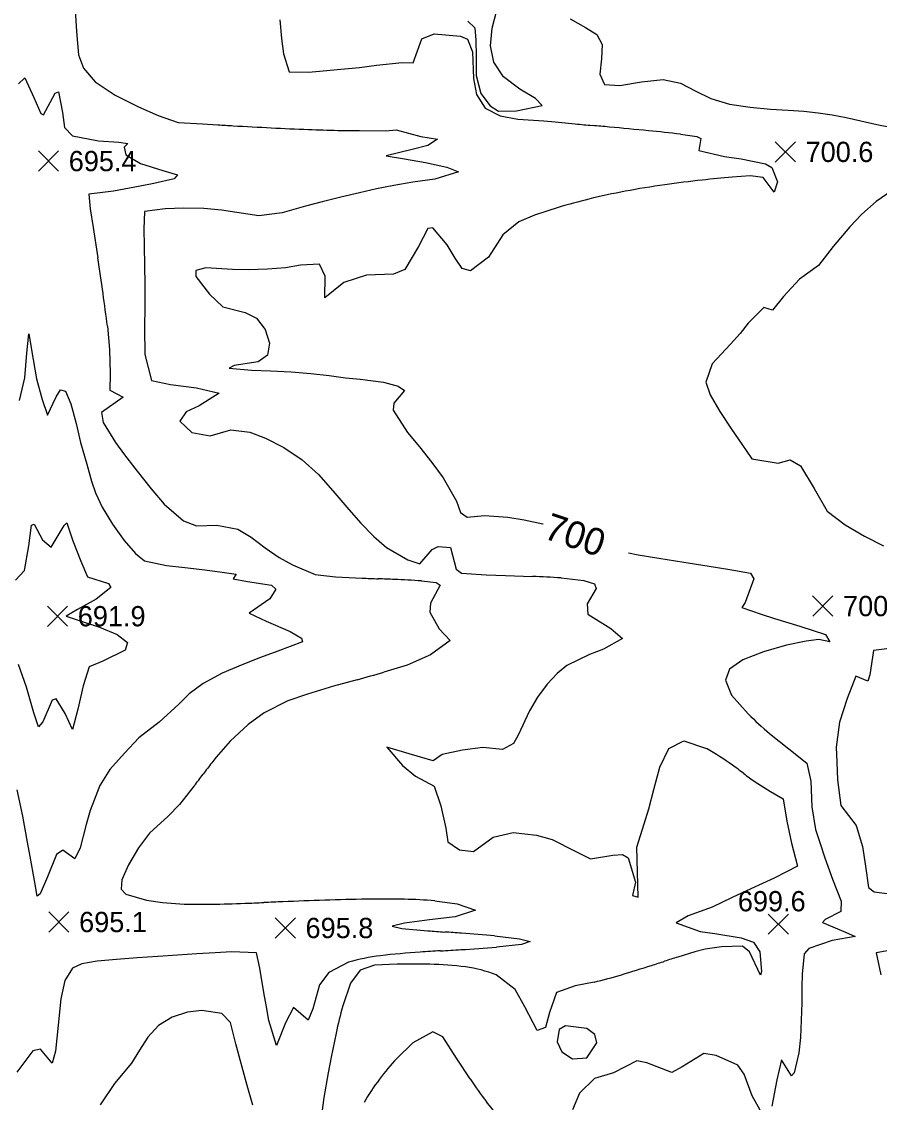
# Model space of a CAD drawing. Extents: x 2566079 to 2571326, y 424054 to 426896.
# Drawn here: x 2567271 to 2567906, y 425294 to 426094 of the extents above; entities that cross this region are included whole.
import ezdxf

# ---------------------------------------------------------------- set-up
doc = ezdxf.new("R2010")
doc.units = 0
for name, color, linetype in [('Contour_ADS_Label_Major', 7, 'Continuous'), ('Contour_ADS_Major', 7, 'Continuous'), ('Contour_ADS_Minor', 7, 'Continuous'), ('Contour_ADS_Spot_Elevation', 7, 'Continuous')]:
    doc.layers.add(name, color=color, linetype=linetype)

# ---------------------------------------------------------------- blocks, each defined once
blk = doc.blocks.new('S750')
at = {"layer": 'Contour_ADS_Spot_Elevation'}
for p, q in [((-0.5, 0.498), (0.5, -0.498)), ((-0.498, -0.5), (0.498, 0.5))]:
    blk.add_line(p, q, dxfattribs=at)

msp = doc.modelspace()

# ---------------------------------------------------------------- linework, layer by layer
at = {"layer": 'Contour_ADS_Major'}
for points in [[(2567462.34, 426095.16), (2567463.66, 426081.33), (2567465.22, 426069.89), (2567469.25, 426056.61), (2567483.55, 426056.31), (2567494.38, 426057.49), (2567507.57, 426058.6), (2567521.31, 426059.91), (2567534.02, 426061.5), (2567553, 426063.65), (2567561, 426063.42), (2567567.4, 426081.06), (2567576.52, 426084.87), (2567596.19, 426083.11), (2567601.2, 426080.96), (2567604.98, 426071.58), (2567605.65, 426051.77), (2567608.08, 426039.79), (2567614.38, 426029.9), (2567625.51, 426024.11), (2567638.68, 426021.59), (2567657.82, 426020.31), (2567666.12, 426019.58), (2567681.09, 426018.16)], [(2567759.03, 426010.59), (2567771.08, 426008.87), (2567774.11, 426007.48), (2567772.56, 425998.57), (2567791.4, 425994.16), (2567803.88, 425992.25), (2567821.79, 425988.7), (2567826.59, 425985.98), (2567830.65, 425975.24), (2567828.36, 425967.78), (2567820.04, 425978.4), (2567810.51, 425979.65), (2567797.15, 425978.78)], [(2567668.45, 425956.35), (2567650.9, 425950.53), (2567639.21, 425945.6), (2567627.37, 425936.13), (2567616.83, 425919.57), (2567603.5, 425909.36), (2567597.34, 425911.15), (2567592.18, 425918.77), (2567586.17, 425928.64), (2567575.71, 425941.37), (2567571.92, 425940.89), (2567565.17, 425927.49), (2567554.83, 425910.41), (2567546.45, 425907.11), (2567526.63, 425906.14), (2567509.79, 425900.74), (2567495.72, 425889.42), (2567496.01, 425905.51), (2567491.79, 425914.35), (2567477.61, 425913.59), (2567466.53, 425911.76), (2567453.23, 425910.62), (2567439.5, 425910.26), (2567427.47, 425910.49), (2567407.77, 425911.78), (2567400.33, 425909.65), (2567400.28, 425905.19), (2567410.49, 425892.32), (2567420.32, 425882.75), (2567436.77, 425878.74), (2567445.09, 425874.4), (2567451.57, 425866.05), (2567454.78, 425855.92), (2567453.28, 425847.19), (2567446.46, 425842.25), (2567428.71, 425839.39), (2567424.95, 425837.34), (2567441.52, 425835.92), (2567455.63, 425835.51), (2567470.88, 425834.81), (2567485.41, 425833.52), (2567498.81, 425831.92), (2567510.99, 425830.39), (2567521.87, 425829.21), (2567539.17, 425827.12), (2567549.88, 425824.08), (2567554.59, 425820.95), (2567546.68, 425811.64), (2567546.21, 425806.44), (2567556.91, 425789.97), (2567565.75, 425779.29), (2567574.98, 425767.65), (2567583.35, 425756.21), (2567593.07, 425739.01), (2567596.05, 425730.63), (2567601.01, 425727.25), (2567613.93, 425728.56), (2567631.26, 425727.3), (2567643.37, 425725.27), (2567657.06, 425722.27), (2567657.23, 425722.23)], [(2567720.39, 425700.91), (2567727.7, 425699.42), (2567742.86, 425696.85), (2567761.33, 425693.9), (2567780.11, 425690.96), (2567795.43, 425688.56), (2567810.75, 425685.73), (2567813.29, 425681.58), (2567806.78, 425664.12), (2567804.33, 425660.5), (2567818.61, 425655.49), (2567828.56, 425652.32), (2567847.24, 425646.53), (2567866.17, 425640.35), (2567869.43, 425634.94), (2567861.34, 425636.71), (2567852.08, 425635.58), (2567837.4, 425632.43), (2567820.39, 425627.59), (2567805.17, 425621.65), (2567795.28, 425614.9), (2567792.19, 425606.57), (2567796.8, 425595.6), (2567809.03, 425581.65)], [(2567824.84, 425567.27), (2567839.16, 425555.73), (2567852.51, 425545.17), (2567855.33, 425531.87), (2567856.17, 425513.01), (2567858.91, 425496.27), (2567862.06, 425486.45), (2567865.85, 425475.16), (2567871.53, 425459.39), (2567877.77, 425443.09), (2567877.55, 425435.4), (2567866.03, 425429.52), (2567863.95, 425427.48), (2567880.98, 425420.33), (2567888.11, 425417.04), (2567871.26, 425413.98), (2567854.01, 425408.1), (2567850.4, 425404.16), (2567849.06, 425389.2), (2567848.86, 425379.81), (2567848.69, 425368.04), (2567848.37, 425355.04), (2567847.68, 425342.24), (2567846.48, 425330.94), (2567843.06, 425316.13), (2567841.15, 425313.85), (2567833.72, 425325.75), (2567830.13, 425311.01), (2567826.49, 425291.4)], [(2567603.32, 425311.59), (2567593.25, 425326.89), (2567582.98, 425342.73), (2567575.74, 425346.51), (2567560.86, 425338.44), (2567549.01, 425326.84)], [(2567820.05, 425284.63), (2567811.99, 425299.22), (2567806, 425315.05), (2567801.34, 425321.76), (2567785.32, 425329.05), (2567776.28, 425330.43), (2567760.12, 425320.52), (2567752.59, 425316.46), (2567734.01, 425323.45), (2567726.56, 425325), (2567709.44, 425316.16), (2567695.41, 425311.87), (2567684.1, 425301.07), (2567678.97, 425288.67)], [(2567626.89, 425280.36), (2567615.34, 425294.59)]]:
    msp.add_lwpolyline(points, dxfattribs=at)
msp.add_lwpolyline([(2567667.64, 425339.06), (2567671.02, 425331.64), (2567678.96, 425326.53), (2567689.66, 425327.29), (2567696.93, 425338.29), (2567695.66, 425344.48), (2567689.7, 425348.94), (2567673.73, 425350.88), (2567669.21, 425348.09), (2567667.64, 425339.06)], close=True, dxfattribs=at)
for centre, radius, start, end in [((2568706.55, 436984.47), 11014.15, 264.657814, 264.723589), ((2566534.64, 413476.57), 12593.87, 84.661939, 84.719464), ((2566982.3, 418237.87), 7811.57, 84.468856, 84.682225), ((2567566.58, 424279.18), 1742.08, 83.65765, 84.44466), ((2567841.53, 425299.9), 679.76, 97.97351, 100.46715), ((2567871.15, 425103.53), 878.34, 96.28207, 98.10999), ((2567858.79, 425243.76), 737.6, 94.79374, 96.51968), ((2567813.93, 425460.03), 517.28, 100.68282, 103.72253), ((2567793.69, 425540.62), 434.19, 103.65118, 106.76536), ((2567988.45, 425763.03), 255.13, 225.31143, 230.11234), ((2567682.02, 425202.72), 181.93, 136.98036, 143.3136), ((2567659.57, 425217.49), 155.11, 142.73318, 150.32027), ((2567967.9, 425556.62), 439.27, 213.9046, 216.62052)]:
    msp.add_arc(centre, radius, start, end, dxfattribs=at)
at = {"layer": 'Contour_ADS_Minor'}
for points in [[(2567246.02, 426227.22), (2567260.29, 426234.98), (2567265.45, 426231.12), (2567270.63, 426234.47), (2567276.99, 426224.58), (2567283.12, 426207.93), (2567287.63, 426192.52), (2567294.86, 426177.28), (2567304.09, 426161.8), (2567306.68, 426151.66), (2567308.54, 426137.36), (2567309.79, 426121.24), (2567310.64, 426106.44), (2567311.82, 426086.51), (2567313.44, 426069.32), (2567317.06, 426059.43), (2567325.67, 426049.24), (2567340.46, 426039.34), (2567357.71, 426030.67), (2567372.46, 426024.26), (2567387.1, 426019.15), (2567405.23, 426018.1), (2567416.59, 426017.44)], [(2567601.46, 426094.19), (2567606.62, 426089.26), (2567607.58, 426080.12), (2567607.76, 426068.22), (2567607.8, 426054.03), (2567611.23, 426040.56), (2567618.19, 426031.46), (2567624.28, 426027.66), (2567637.61, 426027.94), (2567656.62, 426031.85), (2567651.68, 426036.83), (2567640, 426043.95), (2567628, 426053.02), (2567620.82, 426063.77), (2567618.44, 426075.91), (2567619.54, 426089.06), (2567623.1, 426102.39)], [(2567677.28, 426096), (2567688.74, 426089.58), (2567697.02, 426084.23), (2567700.95, 426077.01), (2567700.37, 426066.22), (2567699.27, 426054.93), (2567702.67, 426047.43), (2567713.94, 426046.55), (2567730.02, 426049.21), (2567746.21, 426050.89), (2567759.02, 426048.24), (2567769.85, 426042.69), (2567781.3, 426036.86), (2567795.25, 426032.81), (2567810.61, 426030.45), (2567825.58, 426029.13), (2567838.74, 426028.28), (2567850.31, 426027.5), (2567860.89, 426026.44), (2567871.1, 426024.86), (2567881.44, 426022.8)], [(2567268.91, 426047.81), (2567273.81, 426052.36), (2567280.29, 426037.69), (2567285.61, 426025.95), (2567287.47, 426024.97), (2567296.27, 426040.88), (2567298.68, 426041.97), (2567301.63, 426026.67), (2567303.15, 426015.39), (2567308.96, 426009.31), (2567328.32, 426005.71), (2567343.22, 426004.77), (2567349.9, 426003.64), (2567347.21, 426001.07), (2567348.42, 425995.32), (2567359.36, 425988.79), (2567375.84, 425983.68), (2567386.64, 425980.41), (2567384.26, 425977.59), (2567369.09, 425974.11), (2567359.02, 425972.07), (2567339.41, 425968.45), (2567321.12, 425966.29), (2567322.15, 425955.33), (2567324.26, 425941.54), (2567327.69, 425919.09)], [(2567881.44, 426022.8), (2567892.44, 426020.4), (2567904.25, 426017.83), (2567915.64, 426015.39)], [(2567505.47, 426013.38), (2567521.34, 426013.17), (2567540.93, 426012.93), (2567548.43, 426013.82), (2567566.66, 426008.89), (2567579.1, 426006.83), (2567571.97, 426002.12), (2567560.45, 425999.13), (2567541.09, 425994.61), (2567554.76, 425992.29), (2567570.23, 425989.55), (2567586.1, 425986.11), (2567594.63, 425982.67), (2567577.11, 425977.27), (2567560.94, 425974.96), (2567546.67, 425972.59), (2567533.98, 425970.03), (2567521.28, 425967.16), (2567507.51, 425963.92), (2567493.69, 425960.55), (2567481.37, 425957.36), (2567464.25, 425952.42), (2567446.8, 425950.11), (2567430.49, 425952.58), (2567419.25, 425954.38), (2567406.06, 425955.65), (2567391.46, 425955.89), (2567377.66, 425955.3), (2567362.17, 425953.25), (2567361.81, 425940.18), (2567361.98, 425927.86), (2567362.23, 425913.09), (2567362.47, 425899.6), (2567362.59, 425883.07), (2567362.2, 425866.94), (2567362.48, 425847.55), (2567367.44, 425828.22), (2567381.49, 425825.3), (2567400.81, 425822.8), (2567417.56, 425818.99), (2567402.66, 425809.71), (2567393.05, 425805.12), (2567388.31, 425798.19), (2567397.41, 425789.9), (2567410.78, 425787.31), (2567426.23, 425791.93), (2567440.14, 425790.06), (2567451.74, 425785.63), (2567465.33, 425778.76), (2567478.93, 425769.7), (2567490.99, 425758.77), (2567501.76, 425746.77), (2567511.96, 425734.6), (2567522.12, 425723.11), (2567532.05, 425712.99), (2567541.43, 425704.89), (2567557.08, 425695.71), (2567566.14, 425692.62), (2567575.16, 425703.43), (2567579.56, 425705.6), (2567588.78, 425704.69), (2567592.98, 425688.76), (2567596.75, 425685.74), (2567615.14, 425684.57), (2567629.4, 425684.07), (2567649.36, 425683.38)], [(2567915.53, 425968.98), (2567903.71, 425960.74), (2567893.14, 425951.35), (2567884.21, 425942.06), (2567872.01, 425927.35), (2567861.1, 425913.51), (2567846.91, 425903.4), (2567835.2, 425890.46), (2567826.94, 425880.29), (2567820.65, 425882.26), (2567809.03, 425870.74), (2567803.06, 425863.05), (2567795.87, 425855.25), (2567782.32, 425840.75), (2567777.77, 425827.03), (2567780.9, 425817.67), (2567787.94, 425805.42), (2567796.71, 425792.34), (2567804.42, 425781.19), (2567811.71, 425770.27), (2567831.17, 425767.06), (2567840.23, 425769.53), (2567847.81, 425765.22), (2567857.99, 425748.43), (2567867.57, 425731.71), (2567880.81, 425721.53), (2567895.16, 425713.28), (2567909.11, 425705.91)], [(2567334.77, 425868.42), (2567336.41, 425851.19), (2567336.74, 425833.19), (2567336.6, 425821.3), (2567346.51, 425816.04), (2567330.55, 425804.66), (2567331.63, 425797.22), (2567340.8, 425782.47), (2567347.58, 425773.36), (2567356.78, 425761.24), (2567367.13, 425748.16), (2567376.94, 425736.74), (2567391.22, 425724.49), (2567400.71, 425720.85), (2567415.78, 425721.41), (2567431.36, 425718.36), (2567441.09, 425712.39), (2567451.53, 425704.66), (2567462.02, 425697.28), (2567471.81, 425691.91), (2567488.53, 425684.78), (2567503.57, 425682.98), (2567523.46, 425682.12)], [(2567269.65, 425813.65), (2567273.7, 425830.28), (2567275.24, 425848.61), (2567276.76, 425862.95), (2567279.83, 425843.77), (2567282.38, 425829.54), (2567286.41, 425814.3), (2567290.57, 425802.75), (2567296.85, 425816.17), (2567300.03, 425821.31), (2567303.74, 425820.55), (2567307.73, 425811.08), (2567311.63, 425796.62), (2567315, 425782.5), (2567319.51, 425766.32), (2567323.11, 425753.81), (2567326.07, 425745.16), (2567331.04, 425734.52), (2567338.55, 425722.15), (2567347.3, 425709.97), (2567355.51, 425700.35), (2567362.14, 425694.94), (2567378.44, 425691.38), (2567392.02, 425689.89), (2567407, 425688.16), (2567419.66, 425686.65), (2567430.08, 425684.98), (2567427.86, 425681.72), (2567438.44, 425679.59), (2567456.21, 425676.83), (2567459.43, 425674.06), (2567454.94, 425666.72), (2567439.67, 425656.11), (2567452.41, 425650.17), (2567470.18, 425642.68), (2567478.53, 425637.76), (2567479.29, 425634.88), (2567460.88, 425628.04), (2567448.21, 425623.31), (2567435.15, 425618.3), (2567419.75, 425611.73), (2567405.56, 425604.28), (2567395.21, 425596.55), (2567387.61, 425588.96), (2567373.17, 425575.63), (2567357.97, 425564.07), (2567347.45, 425552.54), (2567336.51, 425540.62), (2567329.26, 425528.72), (2567322.08, 425510.12), (2567319.2, 425499.88), (2567314.61, 425482.71), (2567310.62, 425474.47), (2567301.81, 425480.95), (2567297.06, 425477.79), (2567290.48, 425461.12), (2567285.11, 425448.54), (2567282.74, 425446.87), (2567280.88, 425458.56), (2567277.56, 425476.31), (2567275.65, 425486.82), (2567272.24, 425505.93), (2567267.97, 425525.4)], [(2567266.72, 425680.67), (2567273.47, 425687.73), (2567276.76, 425705.99), (2567278.69, 425721.2), (2567280.72, 425722.14), (2567286.69, 425710.39), (2567293.22, 425704.96), (2567302.73, 425720.99), (2567304.81, 425723.03), (2567309.3, 425709.68), (2567315.16, 425694.7), (2567320.09, 425682.98), (2567335.74, 425678.13), (2567337.43, 425675.11), (2567326.5, 425666.5), (2567312.64, 425658.97), (2567304.24, 425654.02), (2567316.24, 425649.97), (2567328.91, 425645.77), (2567342.05, 425640.36), (2567349.76, 425634.51), (2567347.99, 425628.94), (2567331.39, 425620.59), (2567321.39, 425616.44), (2567316.87, 425602.37), (2567312.88, 425585.25), (2567308.88, 425570.13), (2567303.55, 425581.87), (2567296.97, 425592.75), (2567293.89, 425591.76), (2567286.91, 425575.81), (2567283.69, 425572.22), (2567280.35, 425582.56), (2567274.88, 425601.39), (2567269.04, 425618.18)], [(2567567.24, 425680.1), (2567578.01, 425678.83), (2567581, 425676.93), (2567574.05, 425663.49), (2567573.52, 425657.03), (2567580.26, 425644.5), (2567588.51, 425635.98), (2567574, 425625.35), (2567556.63, 425617.81), (2567539.37, 425612.53)], [(2567670.56, 425682.27), (2567687.29, 425680.49), (2567695.35, 425677.86), (2567696.62, 425674.56), (2567689.84, 425663.02), (2567690.47, 425655.42), (2567707.36, 425644.86), (2567716.11, 425637.58), (2567702.06, 425629.53), (2567691.55, 425625.6), (2567674.86, 425617.49), (2567667.63, 425611.61), (2567660.25, 425603.58), (2567653.15, 425594.05), (2567647.08, 425583.97), (2567638.81, 425565.97), (2567635.25, 425559.84), (2567627.26, 425555.39), (2567612.75, 425556.92), (2567597.66, 425554.82), (2567582.53, 425551.76), (2567575.8, 425547.08), (2567558.24, 425552.08), (2567541.6, 425556.96), (2567553.32, 425543.44), (2567562.91, 425535.54), (2567576.71, 425528.31), (2567581.58, 425513.72), (2567585.3, 425497.06), (2567586.81, 425487.15), (2567595.34, 425481.03), (2567605.7, 425479.83), (2567620.32, 425490.42), (2567635.06, 425493.91), (2567652.44, 425492.03), (2567663.96, 425488.81), (2567681.09, 425480.09), (2567692.25, 425474.52), (2567708.91, 425477.23), (2567716.08, 425477.66), (2567720.14, 425475.1), (2567725.68, 425457.28), (2567723.44, 425447.4), (2567727.68, 425446.18), (2567727.02, 425464.49), (2567726.61, 425483.19), (2567732.08, 425500.43), (2567735.44, 425511.5), (2567739.24, 425525.8), (2567743.57, 425542.2), (2567750.22, 425556.06), (2567761.42, 425561.88), (2567778.24, 425556.18)], [(2567919.35, 425630.89), (2567901.89, 425628.69), (2567899.14, 425610.56), (2567897.53, 425605.83), (2567888.66, 425609.7), (2567882.27, 425593.14), (2567876.58, 425575.68), (2567874.18, 425557.06), (2567874.55, 425545.9), (2567875.21, 425532.98), (2567877.61, 425513.93), (2567888.9, 425499.06), (2567893.76, 425483.48), (2567895.98, 425469.01), (2567898.2, 425453.36), (2567902.37, 425450.16), (2567921.32, 425447.49)], [(2567519.6, 425606.97), (2567502.03, 425602.08), (2567483.02, 425596.27), (2567468.22, 425591.34), (2567450.93, 425582.46), (2567438.91, 425573.92), (2567425.64, 425561.6)], [(2567814.22, 425531.37), (2567825.45, 425524.25), (2567834.96, 425518.9), (2567837.59, 425502.39), (2567841.18, 425486.11), (2567845.63, 425469.15), (2567828.33, 425460.27), (2567810.97, 425452.39), (2567797.29, 425445.91), (2567782.34, 425438.74), (2567764.72, 425432.25), (2567755.81, 425427.09), (2567773.49, 425420.82), (2567784.32, 425419.13), (2567803.94, 425415.96), (2567812.9, 425412.79), (2567817.55, 425405.76), (2567818.94, 425391.23), (2567818.06, 425388.42), (2567809.96, 425405.61), (2567804.84, 425409.92), (2567789.21, 425409.43), (2567777.13, 425407.52), (2567769.5, 425405.61), (2567756.89, 425401.81)], [(2567399.14, 425528.53), (2567388.16, 425514.56), (2567379.77, 425506.04), (2567365.89, 425493.39), (2567357.87, 425482.55), (2567350.35, 425469.93), (2567345.51, 425458.89), (2567344.99, 425451.95), (2567348.41, 425448.23), (2567363.78, 425443.95), (2567375.7, 425442.12), (2567391.52, 425440.99)], [(2567577.18, 425443.34), (2567593.55, 425441.24), (2567607.29, 425436.38), (2567592.07, 425431.65), (2567573.21, 425429.22), (2567554.66, 425426.86), (2567545.64, 425424.71), (2567552.72, 425422.88), (2567572.01, 425421.2)], [(2567621.34, 425417.5), (2567639.9, 425415.37), (2567647.67, 425413.2), (2567641.17, 425411.1), (2567622.81, 425409.11)], [(2567513.16, 425397.96), (2567498.75, 425390.43), (2567491.69, 425381.21), (2567486.95, 425363.58), (2567483.37, 425355.13), (2567472.59, 425364.37), (2567466.71, 425353.04), (2567459.91, 425336.42), (2567454.16, 425354.84), (2567452.44, 425365.02), (2567450.67, 425375.63), (2567447.59, 425393.66), (2567445.19, 425404.82), (2567426.56, 425405.64), (2567414.56, 425405.01), (2567400.93, 425404.17), (2567386.71, 425403.2), (2567372.06, 425402.16), (2567356.9, 425401.13), (2567341.44, 425400.1), (2567327.2, 425398.75), (2567315.95, 425396.7), (2567308.96, 425393.64), (2567303.26, 425384.4), (2567300.43, 425370.82), (2567298.34, 425351.48), (2567296.41, 425332.1), (2567293.88, 425323.33), (2567285.4, 425333.61), (2567279.52, 425332.34), (2567267.72, 425316.68)], [(2567913.35, 425406.75), (2567903.67, 425404.85), (2567907.29, 425388.71)], [(2567549.35, 425396.47), (2567532.59, 425395.71), (2567521.97, 425392.05), (2567514.82, 425382.54), (2567508.96, 425365.64)], [(2567695.03, 425383.22), (2567680.89, 425380.56), (2567667.08, 425375.63), (2567662.11, 425360.83), (2567659.08, 425349.77), (2567652.76, 425347.4), (2567643.68, 425365.07), (2567636.57, 425377.8), (2567622.57, 425388.61)], [(2567442.33, 425292.13), (2567438.29, 425306.78), (2567433.73, 425323.11), (2567429.89, 425337.53), (2567425.88, 425353.3), (2567419.42, 425359.97), (2567404.7, 425362.34), (2567394.09, 425360.94), (2567382.81, 425357.36), (2567372.61, 425351.26), (2567364.76, 425342.64), (2567358.54, 425332.8), (2567352.73, 425323.34), (2567340.01, 425308.35), (2567329.56, 425292.5)], [(2567504.11, 425345.51), (2567500.47, 425327.75), (2567498.12, 425316.22), (2567494.94, 425297.8), (2567492.94, 425282.9)]]:
    msp.add_lwpolyline(points, dxfattribs=at)
for centre, radius, start, end in [((2567808.26, 432762.96), 6756.88, 266.676961, 266.773447), ((2567714.18, 431086.32), 5077.61, 266.76841, 267.08629), ((2567582.68, 428496.58), 2484.53, 267.07919, 267.71379), ((2567534.75, 427369.22), 1356.15, 267.83711, 268.76277), ((2564440.66, 425480.83), 2920.1, 8.10744, 8.63181), ((2566207.7, 425732.36), 1135.26, 6.88341, 8.11686), ((2567620.22, 424923.88), 760.06, 86.20264, 87.803), ((2567851.11, 433630.94), 7955.57, 267.639636, 267.725122), ((2567471.07, 423948.95), 1733.88, 87.48448, 87.87638), ((2567505.1, 424694.12), 987.93, 86.39391, 87.55953), ((2566517.11, 429209.52), 3739.44, 285.55046, 285.86513), ((2567639.67, 425367.17), 289.16, 137.74733, 141.93289), ((2567657.46, 425349.96), 238.99, 54.17734, 59.6421), ((2567740.01, 425289.4), 416.11, 142.02059, 143.48574), ((2567566.87, 425219.76), 397.59, 53.06538, 54.57407), ((2566439.69, 426265.57), 1209.87, 322.46879, 322.9723), ((2567959.47, 425738.27), 252.79, 232.55701, 234.92943), ((2567932.65, 413579.78), 11872.13, 92.109392, 92.258819), ((2567555.74, 423695.81), 1749.08, 90.95252, 91.96803), ((2567538.76, 424679.75), 764.99, 88.80717, 90.90666), ((2567545.3, 425069.74), 374.96, 85.12301, 88.56531), ((2567404.5, 425916.19), 475.38, 268.43479, 270.89016), ((2567383.66, 426885.28), 1444.69, 271.11949, 272.09512), ((2567355.83, 427655.18), 2215.09, 272.08667, 272.45244), ((2568301.04, 404177.34), 21281.78, 92.252142, 92.290186), ((2567668.05, 426708.95), 1291.33, 265.73473, 266.28981), ((2567432.32, 423147.5), 2277.92, 85.85494, 86.16961), ((2567492.16, 423963.75), 1459.47, 84.92188, 85.88169), ((2567605.22, 424825.86), 580.93, 93.84659, 96.76004), ((2567628.51, 424497.08), 910.53, 92.96762, 93.92079), ((2567407.91, 428445.85), 3044.41, 273.26626, 273.55113), ((2567484.65, 427216.56), 1812.72, 273.53704, 274.37126), ((2567556.94, 425242.48), 161.53, 97.14663, 105.72439), ((2567561.05, 424999.57), 397.07, 88.21621, 91.68853), ((2567568.9, 425153.69), 242.8, 82.65594, 88.93651), ((2567278.92, 426835.49), 1511.15, 286.7823, 287.66832), ((2567009.47, 427690.81), 2407.9, 287.60024, 287.8418), ((2568061.19, 424436.96), 1011.7, 107.50473, 108.07929), ((2567587.61, 425300.71), 94.6, 68.31149, 82.51067), ((2567595.21, 425791.36), 420.17, 283.74328, 286.59898), ((2567874.72, 425266.87), 378.86, 164.88777, 168.01959)]:
    msp.add_arc(centre, radius, start, end, dxfattribs=at)

# ---------------------------------------------------------------- block references
at = {"layer": 'Contour_ADS_Spot_Elevation', "xscale": 15, "yscale": 15}
for p in [(2567836.51, 425997.46), (2567291.19, 425990.66), (2567864.26, 425661.46), (2567297.87, 425653.96), (2567298.86, 425427.75), (2567466.44, 425423.3), (2567831.4, 425426.13)]:
    msp.add_blockref('S750', p, dxfattribs=at)

# ---------------------------------------------------------------- texts
at = {"layer": 'Contour_ADS_Label_Major'}
msp.add_text('700', height=20, rotation=341.34924, dxfattribs=at).set_placement((2567656.7, 425711.85))
at = {"layer": 'Contour_ADS_Spot_Elevation'}
for s, p in [('700.6', (2567851.51, 425989.96)), ('695.4', (2567306.19, 425983.16)), ('700.7', (2567879.26, 425653.96)), ('691.9', (2567312.87, 425646.46)), ('699.6', (2567801.39, 425435.63)), ('695.1', (2567313.86, 425420.25)), ('695.8', (2567481.44, 425415.8))]:
    msp.add_text(s, height=15, dxfattribs=at).set_placement(p)

doc.saveas('drawing.dxf')
